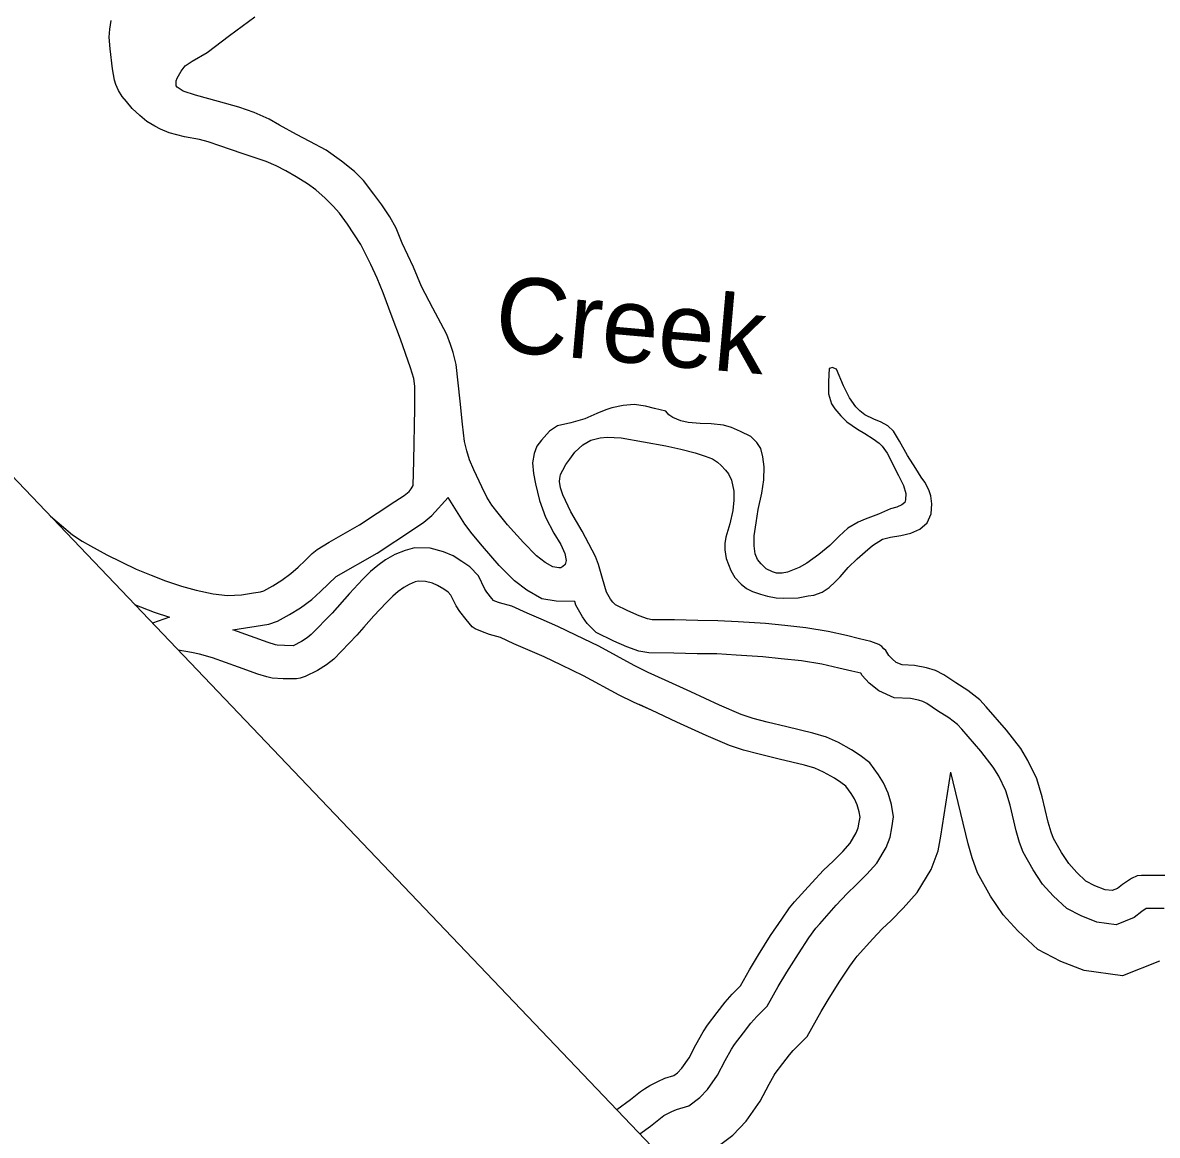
# Model space of a CAD drawing. Extents: x 2104537 to 2336408, y 34176 to 229611.
# Drawn here: x 2135236 to 2137480, y 40170 to 42368 of the extents above; entities that cross this region are included whole.
import ezdxf

# ---------------------------------------------------------------- set-up
doc = ezdxf.new("R2010")
doc.units = 0
for name, color, linetype in [('Exist Boundary Political StateLine', 7, 'Continuous'), ('Exist Hydrographic Buffer Line', 7, 'Continuous'), ('Exist Hydrographic Creek Single Shore', 7, 'Continuous'), ('Exist Hydrographic River Shore', 7, 'Continuous'), ('Old_Level_32', 7, 'Continuous')]:
    doc.layers.add(name, color=color, linetype=linetype)

msp = doc.modelspace()

# ---------------------------------------------------------------- linework, layer by layer
at = {"layer": 'Exist Boundary Political StateLine'}
msp.add_lwpolyline([(2106087.9, 70880.3), (2113861.1, 63060.1), (2116510.3, 60412.5), (2119477.1, 57391), (2125357.5, 51389.4), (2126531.1, 50215.1), (2127676, 49053.2), (2128978.9, 47751.2), (2129985.5, 46727.7), (2130756.4, 45950.7), (2130876.2, 45842.5), (2134634.5, 42081.1), (2139280.4, 37214)], dxfattribs=at)
at = {"layer": 'Exist Hydrographic Buffer Line'}
for points in [[(2135855.9, 41274.1), (2135936.9, 41319.8), (2136008.8, 41367.5), (2136029.2, 41381.3), (2136045.5, 41394.3), (2136077.7, 41430)], [(2136327.9, 41224.8), (2136291, 41225.5), (2136262.6, 41229.9), (2136232.9, 41246.8), (2136208.8, 41265.7), (2136178.6, 41296), (2136145.2, 41333.6), (2136124.9, 41358.6), (2136110.2, 41377.5), (2136077.7, 41430)], [(2136504.1, 40208.8), (2136520.1, 40216.7), (2136528.8, 40220.6), (2136553.6, 40227.9), (2136575, 40244), (2136590.6, 40260.3), (2136610.1, 40288.3), (2136625.3, 40317.3), (2136637.8, 40340.1), (2136643.9, 40349.1), (2136661.3, 40372), (2136676.3, 40390.9), (2136687.6, 40404.2), (2136708.2, 40424.8), (2136729.9, 40463.4), (2136747, 40492.1), (2136770, 40528.4), (2136791, 40559.5), (2136804.5, 40578.7), (2136812.2, 40587.8), (2136844.9, 40624.4), (2136866.4, 40647.2), (2136884.6, 40664.4), (2136905.6, 40685.7), (2136925.3, 40707.7), (2136943.5, 40738.3), (2136951.5, 40758.8), (2136955, 40777.3), (2136958.3, 40798.7), (2136954.2, 40823.1), (2136947.8, 40845.7), (2136938.5, 40865.9), (2136928.6, 40881.7), (2136911.5, 40905.6), (2136892, 40920.5), (2136875.1, 40931.6), (2136849.6, 40945.7), (2136825.9, 40956.7), (2136798.5, 40964.6), (2136747.3, 40976.7), (2136708.6, 40986.1), (2136680.6, 40993.5), (2136657.2, 41001.4), (2136614.1, 41019.9), (2136557.1, 41045.9), (2136506.9, 41069.3), (2136473.1, 41084.5), (2136445.5, 41097.8), (2136375.4, 41136.2), (2136329.9, 41158.1), (2136294.5, 41175.2), (2136261.2, 41189.5), (2136233.7, 41201.2), (2136203.7, 41215), (2136179.3, 41221.7), (2136169.9, 41225.2), (2136167.1, 41226.4), (2136163.8, 41230.4), (2136154.1, 41242.8), (2136150.2, 41248.7), (2136137.5, 41275.1), (2136120.3, 41293), (2136104.8, 41303.7), (2136087.5, 41314.5), (2136068.3, 41323), (2136041.9, 41329.8), (2136010.8, 41330.4), (2135992.3, 41325.6), (2135972, 41317.6), (2135953.9, 41307.1), (2135938.3, 41295.7), (2135923.8, 41283.6), (2135908, 41268), (2135882.3, 41240.5), (2135848.3, 41201.7)], [(2135652, 41168.8), (2135723.1, 41179.6), (2135740.1, 41186), (2135763.9, 41198.6), (2135785.5, 41212.3), (2135807.8, 41228.7), (2135825.4, 41244), (2135855.9, 41274.1)], [(2135457.7, 41218.7), (2135496.4, 41203.4), (2135526.6, 41193.4)], [(2136523.7, 41122.6), (2136474.6, 41122.8), (2136454.3, 41126.7), (2136430.8, 41135.1), (2136405.1, 41146.2), (2136370.2, 41163.6), (2136352.6, 41180.9), (2136343.2, 41194.4), (2136330.2, 41217.2), (2136327.9, 41224.8)], [(2135526.6, 41193.4), (2135493.1, 41181.6)], [(2135848.3, 41201.7), (2135806.9, 41159), (2135799, 41152.6), (2135787.5, 41145.3), (2135770.8, 41137.2), (2135754, 41137.5), (2135739.2, 41138.4), (2135735.9, 41139.2), (2135721.9, 41143.4), (2135652, 41168.8)], [(2137493.2, 40617.6), (2137457.7, 40617.5), (2137449.3, 40612), (2137434, 40599.8), (2137398.6, 40585.7), (2137359.9, 40591.1), (2137329.4, 40603.1), (2137300.6, 40617.9), (2137273.9, 40642.7), (2137252.6, 40666.1), (2137234.2, 40693.9), (2137214.4, 40729.1), (2137207.5, 40748.3), (2137200.7, 40771.4), (2137188.5, 40822.1), (2137180.4, 40850.4), (2137166.2, 40879.1), (2137155.5, 40896.8), (2137130.8, 40928.9), (2137093.1, 40972.2), (2137084.4, 40981.3), (2137067.4, 40994.7), (2137045.3, 41008.6), (2137023.8, 41023), (2137016.4, 41026.9), (2137007.6, 41029.5), (2136991.4, 41032.7), (2136959.5, 41034.2), (2136929.2, 41047.9), (2136910.3, 41063), (2136896.4, 41078.2), (2136893.7, 41082.7), (2136893.3, 41082.9), (2136875.6, 41087.1), (2136850.1, 41093.1), (2136816.3, 41100.9), (2136776.3, 41107.6), (2136736.3, 41111.5), (2136699.5, 41115.4), (2136646.9, 41118.7), (2136608.9, 41121), (2136569.7, 41121.1), (2136523.7, 41122.6)], [(2136456.5, 40172.3), (2136477.8, 40187.7), (2136504.1, 40208.8)]]:
    msp.add_lwpolyline(points, dxfattribs=at)
at = {"layer": 'Exist Hydrographic Creek Single Shore'}
for points in [[(2135553.6, 42233.4), (2135541.6, 42240.8), (2135539.6, 42243.5), (2135539.5, 42253.3), (2135541.6, 42258.9), (2135549.7, 42272.8), (2135557.5, 42283.2), (2135571.4, 42292.7), (2135601.3, 42309.5), (2135645.3, 42343.2), (2135695.2, 42379.9)], [(2135818.6, 41327.5), (2135842.5, 41341.8), (2135902.5, 41375.8), (2135972.3, 41422), (2135990.3, 41434.1), (2136000.3, 41442.1), (2136004.7, 41447), (2136008.1, 41454.1), (2136010, 41502.7), (2136011.7, 41606.6), (2136011.4, 41629), (2136011.5, 41650.3), (2136009.5, 41665.1), (2136003.4, 41686.5), (2135983.1, 41742.7), (2135966.9, 41786.3), (2135948.8, 41834.3), (2135936.9, 41863.4), (2135924.6, 41890.5), (2135904.7, 41930.3), (2135878.6, 41970.2), (2135862.6, 41991.8), (2135850.4, 42006.1), (2135834.3, 42021.9), (2135816.2, 42038), (2135799.7, 42049.8), (2135777, 42064), (2135756.3, 42075.9), (2135737.4, 42085.4), (2135717.9, 42094), (2135670.3, 42109.7), (2135626, 42125.3), (2135602.8, 42133), (2135585.8, 42137.6), (2135556.1, 42143.1), (2135526, 42150.9), (2135508.8, 42157.8), (2135497.7, 42163.9), (2135481.9, 42173.1), (2135467.6, 42184.8), (2135452.8, 42199.2), (2135441.3, 42212.6), (2135432.9, 42222.6), (2135425.6, 42234.8), (2135420.3, 42246.4), (2135417.5, 42254.7), (2135413.6, 42277.1), (2135409.5, 42316.5), (2135407.3, 42340.2), (2135408.6, 42355.9), (2135411.2, 42372.9)], [(2136738.1, 41280.3), (2136726.6, 41280.5), (2136718.8, 41282.9), (2136706.4, 41289.1), (2136696.4, 41299.1), (2136689.4, 41307.4), (2136684.7, 41319), (2136682.4, 41334.5), (2136682.4, 41354.2), (2136686.5, 41380.3), (2136690.3, 41406.5), (2136697.5, 41438.5), (2136701.9, 41464.7), (2136702.1, 41490.9), (2136699.9, 41510.7), (2136695.9, 41527.2), (2136687.9, 41538.8), (2136675.7, 41550.5), (2136655.9, 41560.7), (2136637.7, 41568.3), (2136621.7, 41572.9), (2136597.8, 41575.6), (2136575.8, 41576.1), (2136551.9, 41578.2), (2136537.8, 41581.7), (2136521.5, 41587.9), (2136513.8, 41593.7), (2136507.7, 41600.4), (2136485.8, 41605.7), (2136467.8, 41610.3), (2136445.6, 41614), (2136423.6, 41611.8), (2136401.5, 41607.3), (2136389.6, 41603.6), (2136371.7, 41595.8), (2136347.6, 41585.4), (2136319.9, 41577.7), (2136293.5, 41571.7), (2136277.9, 41561.5), (2136261.8, 41543.7), (2136253, 41531.4), (2136247.8, 41516.8), (2136244.2, 41498.8), (2136246.1, 41477.4), (2136250, 41457), (2136257.9, 41424.1), (2136270.3, 41391), (2136286.5, 41359.5), (2136300.5, 41336.9), (2136308.3, 41319.7), (2136310.7, 41305.6), (2136308.6, 41297.4), (2136304.5, 41293.5), (2136300.6, 41291), (2136296.6, 41291.1), (2136284.5, 41292.9), (2136269.6, 41301.4), (2136252.5, 41314.9), (2136226.4, 41341), (2136195.2, 41376), (2136176.3, 41399.4), (2136164.2, 41415), (2136154.3, 41431), (2136144.2, 41450.9), (2136128.1, 41484.6), (2136120, 41504.5), (2136114.4, 41522.6), (2136109.8, 41540.8), (2136105.6, 41574.7), (2136101.5, 41620.7), (2136097.3, 41656.8), (2136093.4, 41693), (2136087.3, 41716.8), (2136082.4, 41732.6), (2136075.2, 41752.4), (2136063.1, 41774.6), (2136047, 41804.5), (2136024.8, 41846.9), (2136008.8, 41885), (2135986.8, 41933), (2135974.6, 41962.7), (2135962.2, 41985), (2135946.2, 42008.2), (2135930.3, 42029.9), (2135910.1, 42056.5), (2135892.1, 42074.2), (2135866.6, 42095.1), (2135836.1, 42116.3), (2135804, 42134), (2135778, 42147.7), (2135743.9, 42165.7), (2135723.8, 42177.6), (2135693.8, 42191.3), (2135663.9, 42201.7), (2135623.7, 42213), (2135577.7, 42225.3), (2135553.6, 42233.4)], [(2136507.7, 41532.4), (2136537.7, 41525.9), (2136565.8, 41518.2), (2136586, 41511.9), (2136600, 41506.7), (2136610.1, 41499.9), (2136617.2, 41493.2), (2136626.2, 41484.2), (2136631.9, 41476.6), (2136637.9, 41464.3), (2136642.1, 41442.9), (2136642.1, 41424.8), (2136640.4, 41404.2), (2136634.3, 41378.1), (2136626.3, 41352), (2136624.7, 41338.9), (2136624.5, 41326.7), (2136627.4, 41309.3), (2136636.5, 41286.1), (2136644.7, 41272.2), (2136656.6, 41258.9), (2136667.6, 41250.4), (2136679, 41244.3), (2136695.3, 41239.1), (2136708.7, 41234.9), (2136726.3, 41231.9), (2136740.7, 41231), (2136769.3, 41232.1), (2136789.7, 41235.6), (2136800.9, 41237), (2136816.8, 41243.3), (2136831.1, 41252.2), (2136842.8, 41263.5), (2136852.8, 41273.1), (2136868.6, 41291.5), (2136886.6, 41309.2), (2136902.3, 41323), (2136916.3, 41334.9), (2136936.3, 41347.6), (2136952.4, 41351.6), (2136972.5, 41355.1), (2136992.3, 41359.7), (2137010.5, 41367.5), (2137024.5, 41379.7), (2137032.4, 41397.6), (2137034.1, 41417.9), (2137032.1, 41433.7), (2137028, 41445.3), (2137019.8, 41460.2), (2137013.1, 41470.2), (2137002, 41487.5), (2136986, 41513.4), (2136969.9, 41541.6), (2136957.8, 41561.5), (2136946.8, 41571.5), (2136933.5, 41579), (2136919.5, 41585.2), (2136901.6, 41593.7), (2136891.6, 41601.2), (2136883.6, 41609.5), (2136871.4, 41627.1), (2136859.4, 41651), (2136845.3, 41683.4), (2136837.1, 41686.9), (2136833.8, 41685.9), (2136831.2, 41685.3), (2136829.4, 41659.1), (2136829.6, 41635.2), (2136835.4, 41615.4), (2136841.8, 41605.4), (2136853.7, 41591.4), (2136865.6, 41579.7), (2136887, 41565.1), (2136901.6, 41556.7), (2136917.8, 41545.8), (2136929.7, 41537.4), (2136935.9, 41531.4), (2136945.8, 41517.4), (2136967.9, 41473.3), (2136978, 41453.5), (2136982.3, 41438), (2136982.1, 41425.5), (2136980.3, 41420), (2136974.3, 41415.8), (2136964.4, 41411.1), (2136952.2, 41407.4), (2136928.4, 41397), (2136902.2, 41387), (2136888.3, 41381.4), (2136868.1, 41369.6), (2136850.4, 41353.6), (2136832.3, 41334.9), (2136810.3, 41317.2), (2136786.7, 41300.6), (2136771.8, 41291.7), (2136748.6, 41282.3), (2136738.1, 41280.3)], [(2136525, 41188.2), (2136481, 41188.4), (2136471.5, 41190.2), (2136454.9, 41196.1), (2136432.8, 41205.8), (2136408.7, 41217.7), (2136402.9, 41223.4), (2136398.8, 41229.4), (2136390.9, 41243.3), (2136382.8, 41269.7), (2136374.9, 41297.8), (2136368.9, 41313.6), (2136342.3, 41363.4), (2136320.4, 41401.5), (2136304, 41435.3), (2136300, 41449.5), (2136298, 41461.7), (2136298.1, 41467.6), (2136299.9, 41475.7), (2136304, 41483.9), (2136310.1, 41495.2), (2136318.2, 41505.6), (2136327.9, 41519.5), (2136343.6, 41534), (2136359.9, 41543.5), (2136378, 41548.1), (2136391.8, 41549.4), (2136419.7, 41547.9), (2136507.7, 41532.4)], [(2135291.5, 41392.9), (2135334.5, 41356.6), (2135353.6, 41343.7), (2135370.2, 41334.5), (2135402.6, 41316.5), (2135460.8, 41288.5), (2135490.1, 41276.4), (2135518.8, 41265.1), (2135550.4, 41254.6), (2135579.5, 41246.8), (2135612.8, 41239.6), (2135641.3, 41236.4), (2135668.9, 41237.6), (2135692.9, 41241.4), (2135706.4, 41243.4), (2135713, 41245.9), (2135730.9, 41255.4), (2135748.5, 41266.5), (2135766.8, 41280), (2135780.8, 41292.2), (2135794.5, 41305.7), (2135808.6, 41319.5), (2135818.6, 41327.5)], [(2136466.1, 40261.7), (2136476.1, 40268.1), (2136492, 40276), (2136505.9, 40282.3), (2136523.7, 40287.5), (2136531.3, 40293.3), (2136539.7, 40302), (2136553.9, 40322.4), (2136567.5, 40348.4), (2136581.8, 40374.3), (2136590.6, 40387.3), (2136609.4, 40412.2), (2136625.6, 40432.6), (2136639.3, 40448.7), (2136655.4, 40464.8), (2136673.1, 40496.3), (2136691, 40526.5), (2136715.1, 40564.4), (2136737, 40596.8), (2136752.5, 40618.8), (2136762.6, 40630.7), (2136796.5, 40668.8), (2136819.9, 40693.6), (2136838.7, 40711.3), (2136857.7, 40730.6), (2136872.2, 40746.7), (2136884.4, 40767.2), (2136888.2, 40777), (2136890.4, 40788.4), (2136891.9, 40798.2), (2136890.1, 40808.8), (2136886.1, 40822.9), (2136880.7, 40834.5), (2136874.1, 40845.2), (2136863.8, 40859.5), (2136854.1, 40866.9), (2136841.2, 40875.3), (2136819.7, 40887.2), (2136802.8, 40895.1), (2136781.9, 40901.1), (2136732, 40912.9), (2136692.5, 40922.5), (2136661.8, 40930.6), (2136633.7, 40940), (2136587.5, 40960), (2136529.6, 40986.3), (2136479.5, 41009.6), (2136445.4, 41025), (2136415.5, 41039.4), (2136345.3, 41077.8), (2136301.5, 41099), (2136267.3, 41115.4), (2136235.4, 41129.2), (2136207.1, 41141.2), (2136181.1, 41153.2), (2136159.2, 41159.2), (2136145.2, 41164.4), (2136131.2, 41170.6), (2136125.1, 41174.6), (2136112.9, 41189), (2136100.7, 41204.6), (2136093.1, 41216.2), (2136083, 41237.1), (2136077.5, 41242.8), (2136068.7, 41248.9), (2136056.8, 41256.3), (2136046.7, 41260.8), (2136033, 41264.3), (2136018.5, 41264.6), (2136012.6, 41263.1), (2136000.7, 41258.4), (2135989.7, 41252), (2135978.7, 41244), (2135968.1, 41235.1), (2135955, 41222.2), (2135930.9, 41196.4), (2135911.1, 41173.8), (2135897, 41157.7)], [(2136443, 41026.2), (2136415.5, 41039.4), (2136345.3, 41077.8), (2136301.5, 41099), (2136267.3, 41115.4), (2136235.4, 41129.2), (2136207.1, 41141.2), (2136181.1, 41153.2), (2136159.2, 41159.2), (2136145.2, 41164.4), (2136131.2, 41170.6), (2136125.1, 41174.6), (2136112.9, 41189), (2136100.7, 41204.6), (2136093.1, 41216.2), (2136083, 41237.1), (2136077.5, 41242.8), (2136068.7, 41248.9), (2136056.8, 41256.3), (2136046.7, 41260.8), (2136033, 41264.3), (2136018.5, 41264.6), (2136012.6, 41263.1), (2136000.7, 41258.4), (2135989.7, 41252), (2135978.7, 41244), (2135968.1, 41235.1), (2135955, 41222.2), (2135930.9, 41196.4), (2135911.1, 41173.8), (2135897, 41157.7)], [(2137494.4, 40683.2), (2137448.4, 40683.1), (2137439.6, 40682.6), (2137428.6, 40676.9), (2137410.7, 40665.2), (2137400.7, 40657.1), (2137390.4, 40653.1), (2137376.7, 40655), (2137356.5, 40662.9), (2137338.6, 40672.1), (2137320.6, 40688.9), (2137304.5, 40706.6), (2137290.2, 40728.2), (2137274.3, 40756.4), (2137269.9, 40768.6), (2137264.1, 40788.4), (2137251.9, 40838.8), (2137241.8, 40874.2), (2137223.8, 40910.6), (2137209.8, 40933.8), (2137181.6, 40970.5), (2137141.5, 41016.5), (2137128.6, 41029.9), (2137105.4, 41048.4), (2137081.1, 41063.6), (2137057.4, 41079.5), (2137041.2, 41088), (2137023.2, 41093.3), (2136999.4, 41098), (2136975.1, 41099.1), (2136963.7, 41104.3), (2136955.3, 41111), (2136949.2, 41117.7), (2136943.2, 41127.7), (2136939.3, 41131), (2136935.1, 41135.4), (2136929, 41139.4), (2136913, 41145.6), (2136890.8, 41151), (2136865, 41157.1), (2136829, 41165.3), (2136784.9, 41172.7), (2136743, 41176.8), (2136705, 41180.8), (2136650.9, 41184.1), (2136610.9, 41186.6), (2136570.9, 41186.7), (2136525, 41188.2)], [(2135897, 41157.7), (2135851.2, 41110.3), (2135837.2, 41099.1), (2135819.5, 41088), (2135795, 41076), (2135785.1, 41072.9), (2135777.6, 41071.4), (2135751.3, 41071.9), (2135729.4, 41073.3), (2135718.9, 41075.8), (2135701.3, 41081.1), (2135663.2, 41094.9), (2135611.3, 41113.3), (2135585.6, 41120.4), (2135569.9, 41124), (2135543.8, 41128.5)], [(2136466.1, 40261.7), (2136476.1, 40268.1), (2136492, 40276), (2136505.9, 40282.3), (2136523.7, 40287.5), (2136531.3, 40293.3), (2136539.7, 40302), (2136553.9, 40322.4), (2136567.5, 40348.4), (2136581.8, 40374.3), (2136590.6, 40387.3), (2136609.4, 40412.2), (2136625.6, 40432.6), (2136639.3, 40448.7), (2136655.4, 40464.8), (2136673.1, 40496.3), (2136691, 40526.5), (2136715.1, 40564.4), (2136737, 40596.8), (2136752.5, 40618.8), (2136762.6, 40630.7), (2136796.5, 40668.8), (2136819.9, 40693.6), (2136838.7, 40711.3), (2136857.7, 40730.6), (2136872.2, 40746.7), (2136884.4, 40767.2), (2136888.2, 40777), (2136890.4, 40788.4), (2136891.9, 40798.2), (2136890.1, 40808.8), (2136886.1, 40822.9), (2136880.7, 40834.5), (2136874.1, 40845.2), (2136863.8, 40859.5), (2136854.1, 40866.9), (2136841.2, 40875.3), (2136819.7, 40887.2), (2136802.8, 40895.1), (2136781.9, 40901.1), (2136732, 40912.9), (2136692.5, 40922.5), (2136661.8, 40930.6), (2136633.7, 40940), (2136587.5, 40960), (2136529.6, 40986.3), (2136479.5, 41009.6), (2136455, 41020.7)], [(2136410.8, 40220.3), (2136438.1, 40240), (2136458.1, 40256), (2136466.1, 40261.7)]]:
    msp.add_lwpolyline(points, dxfattribs=at)
at = {"layer": 'Exist Hydrographic River Shore'}
for points in [[(2136598.5, 40138.5), (2136640.4, 40170.1), (2136667, 40197.6), (2136694.4, 40237.2), (2136712, 40270.8), (2136721.9, 40288.6), (2136724, 40291.7), (2136739.1, 40311.7), (2136752.3, 40328.3), (2136760, 40337.4), (2136787.4, 40364.9), (2136815.1, 40414.2), (2136830.8, 40440.6), (2136852.3, 40474.5), (2136872, 40503.5), (2136882.5, 40518.5), (2136886.6, 40523.3), (2136917.4, 40557.9), (2136936, 40577.6), (2136953.4, 40594), (2136977.3, 40618.3), (2137004.9, 40649.1), (2137032.3, 40694.9), (2137046.5, 40731.5), (2137052, 40760.6), (2137071.5, 40887.5)], [(2137484.1, 40513.8), (2137410.7, 40484.6), (2137334.8, 40495.2), (2137288.7, 40513.3), (2137243.5, 40536.6), (2137203.8, 40573.4), (2137174.7, 40605.5), (2137150.2, 40642.5), (2137124.5, 40688.1), (2137113.9, 40717.8), (2137105.6, 40745.9), (2137071.5, 40887.5)]]:
    msp.add_lwpolyline(points, dxfattribs=at)

# ---------------------------------------------------------------- texts
at = {"layer": 'Old_Level_32'}
msp.add_text('Creek', height=150, rotation=354.9821, dxfattribs=at).set_placement((2136165.8, 41720.3))

doc.saveas('drawing.dxf')
